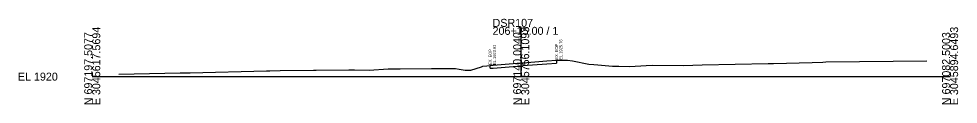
# Model space of a CAD drawing. Extents: x -26 to 19003, y -31 to 24541.
# Drawn here: x 1974.3 to 2302.8, y 8990.3 to 9020.3 of the extents above; entities that cross this region are included whole.
import ezdxf

# ---------------------------------------------------------------- set-up
doc = ezdxf.new("R2010")
doc.units = 0
for name, color, linetype in [('DESIGN - SHEET - Light Grid', 7, 'Continuous'), ('SURVEY - GROUND - Existing Pavement Layer', 7, 'Continuous'), ('SURVEY - GROUND - Existing Pavement Text', 7, 'Continuous'), ('SURVEY - GROUND - Top of Ground', 7, 'Continuous')]:
    doc.layers.add(name, color=color, linetype=linetype)

msp = doc.modelspace()

# ---------------------------------------------------------------- linework, layer by layer
at = {"layer": 'DESIGN - SHEET - Light Grid'}
for p, q in [((2150, 9000), (2150, 9017.46)), ((2000, 9000), (2150, 9000)), ((2150, 9000), (2300, 9000))]:
    msp.add_line(p, q, dxfattribs=at)
at = {"layer": 'SURVEY - GROUND - Existing Pavement Layer'}
for p, q in [((2162.38, 9005.76), (2162.38, 9004.76)), ((2139.18, 9002.93), (2139.18, 9003.93)), ((2139.18, 9002.93), (2139.65, 9002.97)), ((2139.65, 9002.97), (2140.21, 9003)), ((2140.21, 9003), (2150, 9003.8)), ((2150, 9003.8), (2150.63, 9003.85)), ((2150.63, 9003.85), (2158.93, 9004.5)), ((2158.93, 9004.5), (2162.38, 9004.76))]:
    msp.add_line(p, q, dxfattribs=at)
at = {"layer": 'SURVEY - GROUND - Top of Ground'}
msp.add_lwpolyline([(2009.34, 9000.85), (2030.73, 9001.29), (2034.21, 9001.38), (2060.9, 9002.07), (2061.63, 9002.09), (2062.11, 9002.08), (2065.75, 9002.13), (2077.4, 9002.25), (2077.88, 9002.26), (2078.35, 9002.27), (2089.72, 9002.39), (2090.75, 9002.42), (2091.75, 9002.44), (2096.86, 9002.29), (2103.49, 9002.71), (2107.67, 9002.73), (2118.67, 9002.8), (2123.16, 9002.82), (2127.04, 9002.85), (2128.37, 9002.59), (2130.42, 9002.27), (2131.28, 9002.27), (2132.42, 9002.29), (2136.17, 9003.48), (2136.56, 9003.62), (2138.01, 9003.79), (2139.18, 9003.93), (2139.65, 9003.97), (2140.21, 9004), (2150, 9004.8), (2150.63, 9004.85), (2158.93, 9005.5), (2162.38, 9005.76), (2163.25, 9005.8), (2163.57, 9005.82), (2165.58, 9005.81), (2166.24, 9005.79), (2167.95, 9005.58), (2173.65, 9004.36), (2175.39, 9004.2), (2176.77, 9004.13), (2180.69, 9003.81), (2181.91, 9003.69), (2184.19, 9003.66), (2188.04, 9003.51), (2193.77, 9003.93), (2195.83, 9004.02), (2206.81, 9003.94), (2213.33, 9004.13), (2236.33, 9004.57), (2238.29, 9004.64), (2251.72, 9005), (2255.52, 9005.13), (2256.51, 9005.15), (2291.91, 9005.5)], dxfattribs=at)

# ---------------------------------------------------------------- texts
at = {"layer": 'DESIGN - SHEET - Light Grid'}
for s, p in [('DSR107', (2140, 9017.46)), ('206+15.00 / 1', (2140, 9014.66)), ('EL 1920', (1974, 8998.6))]:
    msp.add_text(s, height=2.8, dxfattribs=at).set_placement(p)
for s, p in [('N 697197.5077', (2000, 8990)), ('E 3045617.5694', (2002.8, 8990)), ('N 697140.0040', (2150, 8990)), ('E 3045756.1093', (2152.8, 8990)), ('N 697082.5003', (2300, 8990)), ('E 3045894.6493', (2302.8, 8990))]:
    msp.add_text(s, height=2.8, rotation=90, dxfattribs=at).set_placement(p)
at = {"layer": 'SURVEY - GROUND - Existing Pavement Text'}
for s, p in [('EL.1925.76', (2164.38, 9005.96)), ('EX. EOP', (2139.68, 9004.13)), ('EL.1923.93', (2141.18, 9004.13)), ('EX. EOP', (2162.88, 9005.96))]:
    msp.add_text(s, height=1, rotation=90, dxfattribs=at).set_placement(p)

doc.saveas('drawing.dxf')
